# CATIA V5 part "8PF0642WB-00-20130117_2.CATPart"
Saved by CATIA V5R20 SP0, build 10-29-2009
Part number: 8PF0642WB-00-20130117_2
Revision: ANY
Definition: UNKNOWN
Nomenclature: 8PF0642WB-00-20130117_2
Source: Unknown
Bounding box of the stored display mesh (mm): x 1758.657 to 1958.657, y 1464.879 to 1471.765, z 0 to 6
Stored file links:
  C:\Users\Utente\Desktop\IO LAVORO\3D X SITO CF\CUMSA\3D files PF\PF 0642WB\8PF0642WB-00-20130117_2.CATPart
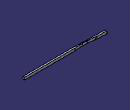
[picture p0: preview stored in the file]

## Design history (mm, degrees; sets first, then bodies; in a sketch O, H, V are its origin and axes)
Body1 "Cortar-Extruir1" (main body)
  Solid1: solid without history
